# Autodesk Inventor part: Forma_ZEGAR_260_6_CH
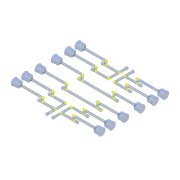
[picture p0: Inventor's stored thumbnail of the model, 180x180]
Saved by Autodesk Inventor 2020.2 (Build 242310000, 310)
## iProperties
Created: 2015-01
Part Number: Forma_ZEGAR_260_6_CH
Material: Ogólny
Document SubType Name: Modeling
Designer: F.Stasiak
Density: 1 g/cm^3
Appearance: Przezroczysty - niebieski
Catalog Web Link: www.expertbooks.pl
Manager: www.cadconsulting.pl
Company: Fabian Stasiak CAD Consulting
Author: F.Stasiak
Subject: Zbiór ćwiczeń. Autodesk Inventor 2020. Kurs Professional
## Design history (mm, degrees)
node "Płaszczyzna konstrukcyjna1"
node "Segment chłodzenia1"
  sketch "Szkic1"
    geometry: L1 (0, 0)-(0, -5.177); L2 (0, -5.177)-(6.924, -4.745); L3 (6.924, -4.745)-(6.924, -4); L4 (6.924, -4)-(149.076, -4); L5 (149.076, -4)-(149.076, -4.745); L6 (149.076, -4.745)-(156, -5.177); L7 (156, -5.177)-(156, 0); L8 (0, 0)-(156, 0)
    constraints: 16 end point, 4 perpendicular, 1 parallel
    dimensions: "d0" = 4 distance between parallel lines of L4 L8; "d1" = 6.92404 distance between parallel lines of L3 L1; "d2" = 6.92404 distance between parallel lines of L5 L7; "d3" = 93.5763 deg angle of L2 L3; "d4" = 0.74472 distance of L2.end L3.end; "d5" = 93.5763 deg angle of L6 L5; "d6" = 0.74472 distance of L4.end L5.end
  node "Punkt konstrukcyjny1"
  node "Oś konstrukcyjna1"
node "Płaszczyzna konstrukcyjna3"
node "Segment chłodzenia3"
  sketch "Szkic3"
    geometry: L1 (0, 0)-(0, -5.177); L2 (0, -5.177)-(6.924, -4.745); L3 (6.924, -4.745)-(6.924, -4); L4 (6.924, -4)-(68, -4); L5 (68, -4)-(70.403, 0); L6 (70.403, 0)-(68, 0); L7 (0, 0)-(68, 0)
    constraints: 14 end point, 2 perpendicular, 1 collinear, 1 parallel
    dimensions: "d18" = 4 distance between parallel lines of L4 L7; "d19" = 2.40344 distance of L5.end L6.end; "d20" = 6.92404 distance between parallel lines of L3 L1; "d21" = 93.5763 deg angle of L2 L3; "d22" = 0.74472 distance of L2.end L3.end; "d23" = 59 deg angle of L5 L7
  node "Punkt konstrukcyjny3"
  node "Oś konstrukcyjna3"
node "Płaszczyzna konstrukcyjna4"
node "Segment chłodzenia4"
  sketch "Szkic4"
    geometry: L1 (0, 0)-(0, -5.177); L2 (0, -5.177)-(6.924, -4.745); L3 (6.924, -4.745)-(6.924, -4); L4 (6.924, -4)-(68, -4); L5 (68, -4)-(70.403, 0); L6 (70.403, 0)-(68, 0); L7 (0, 0)-(68, 0)
    constraints: 14 end point, 2 perpendicular, 1 collinear, 1 parallel
    dimensions: "d26" = 4 distance between parallel lines of L4 L7; "d27" = 2.40344 distance of L5.end L6.end; "d28" = 6.92404 distance between parallel lines of L3 L1; "d29" = 93.5763 deg angle of L2 L3; "d30" = 0.74472 distance of L2.end L3.end; "d31" = 59 deg angle of L5 L7
  node "Punkt konstrukcyjny4"
  node "Oś konstrukcyjna4"
node "Płaszczyzna konstrukcyjna5"
node "Segment chłodzenia5"
  sketch "Szkic5"
    geometry: L1 (0, 0)-(0, -5.177); L2 (0, -5.177)-(6.924, -4.745); L3 (6.924, -4.745)-(6.924, -4); L4 (6.924, -4)-(75, -4); L5 (75, -4)-(77.403, 0); L6 (77.403, 0)-(75, 0); L7 (0, 0)-(75, 0)
    constraints: 14 end point, 2 perpendicular, 1 collinear, 1 parallel
    dimensions: "d34" = 4 distance between parallel lines of L4 L7; "d35" = 2.40344 distance of L5.end L6.end; "d36" = 6.92404 distance between parallel lines of L3 L1; "d37" = 93.5763 deg angle of L2 L3; "d38" = 0.74472 distance of L2.end L3.end; "d39" = 59 deg angle of L5 L7
  node "Punkt konstrukcyjny5"
  node "Oś konstrukcyjna5"
node "Płaszczyzna konstrukcyjna6"
node "Segment chłodzenia6"
  sketch "Szkic6"
    geometry: L1 (0, 0)-(0, -4); L2 (0, -4)-(7, -4); L3 (7, -4)-(9.403, 0); L4 (9.403, 0)-(7, 0); L5 (0, 0)-(7, 0)
    constraints: 10 end point, 1 collinear, 1 parallel, 1 perpendicular
    dimensions: "d42" = 4 distance between parallel lines of L2 L5; "d43" = 2.40344 distance of L3.end L4.end; "d44" = 59 deg angle of L3 L5
  node "Punkt konstrukcyjny6"
  node "Oś konstrukcyjna6"
node "Płaszczyzna konstrukcyjna7"
node "Segment chłodzenia7"
  sketch "Szkic7"
    geometry: L1 (0, 0)-(0, -4); L2 (0, -4)-(7, -4); L3 (7, -4)-(9.403, 0); L4 (9.403, 0)-(7, 0); L5 (0, 0)-(7, 0)
    constraints: 10 end point, 1 collinear, 1 parallel, 1 perpendicular
    dimensions: "d47" = 4 distance between parallel lines of L2 L5; "d48" = 2.40344 distance of L3.end L4.end; "d49" = 59 deg angle of L3 L5
  node "Punkt konstrukcyjny7"
  node "Oś konstrukcyjna7"
node "Płaszczyzna konstrukcyjna9"
node "Segment chłodzenia9"
  sketch "Szkic9"
    geometry: L1 (0, 0)-(0, -4); L2 (0, -4)-(12, -4); L3 (12, -4)-(14.403, 0); L4 (14.403, 0)-(12, 0); L5 (0, 0)-(12, 0)
    constraints: 10 end point, 1 collinear, 1 parallel, 1 perpendicular
    dimensions: "d57" = 4 distance between parallel lines of L2 L5; "d58" = 2.40344 distance of L3.end L4.end; "d59" = 59 deg angle of L3 L5
  node "Punkt konstrukcyjny9"
  node "Oś konstrukcyjna9"
node "Płaszczyzna konstrukcyjna10"
node "Segment chłodzenia10"
  sketch "Szkic10"
    geometry: L1 (0, 0)-(0, -4); L2 (0, -4)-(12, -4); L3 (12, -4)-(14.403, 0); L4 (14.403, 0)-(12, 0); L5 (0, 0)-(12, 0)
    constraints: 10 end point, 1 collinear, 1 parallel, 1 perpendicular
    dimensions: "d62" = 4 distance between parallel lines of L2 L5; "d63" = 2.40344 distance of L3.end L4.end; "d64" = 59 deg angle of L3 L5
  node "Punkt konstrukcyjny10"
  node "Oś konstrukcyjna10"
node "Płaszczyzna konstrukcyjna12"
node "Segment chłodzenia12"
  sketch "Szkic12"
    geometry: L1 (0, 0)-(0, -5.177); L2 (0, -5.177)-(6.924, -4.745); L3 (6.924, -4.745)-(6.924, -4); L4 (6.924, -4)-(68, -4); L5 (68, -4)-(70.403, 0); L6 (70.403, 0)-(68, 0); L7 (0, 0)-(68, 0)
    constraints: 14 end point, 2 perpendicular, 1 collinear, 1 parallel
    dimensions: "d72" = 4 distance between parallel lines of L4 L7; "d73" = 2.40344 distance of L5.end L6.end; "d74" = 6.92404 distance between parallel lines of L3 L1; "d75" = 93.5763 deg angle of L2 L3; "d76" = 0.74472 distance of L2.end L3.end; "d77" = 59 deg angle of L5 L7
  node "Punkt konstrukcyjny12"
  node "Oś konstrukcyjna12"
node "Płaszczyzna konstrukcyjna13"
node "Segment chłodzenia13"
  sketch "Szkic13"
    geometry: L1 (0, 0)-(0, -5.178); L2 (0, -5.178)-(6.924, -4.744); L3 (6.924, -4.744)-(6.924, -4); L4 (6.924, -4)-(68, -4); L5 (68, -4)-(70.403, 0); L6 (70.403, 0)-(68, 0); L7 (0, 0)-(68, 0)
    constraints: 14 end point, 2 perpendicular, 1 collinear, 1 parallel
    dimensions: "d80" = 4 distance between parallel lines of L4 L7; "d81" = 2.40344 distance of L5.end L6.end; "d82" = 6.924 distance between parallel lines of L3 L1; "d83" = 93.58 deg angle of L2 L3; "d84" = 0.7445 distance of L2.end L3.end; "d85" = 59 deg angle of L5 L7
  node "Punkt konstrukcyjny13"
  node "Oś konstrukcyjna13"
node "Płaszczyzna konstrukcyjna14"
node "Segment chłodzenia14"
  sketch "Szkic14"
    geometry: L1 (0, 0)-(0, -5.178); L2 (0, -5.178)-(6.924, -4.745); L3 (6.924, -4.745)-(6.924, -4); L4 (6.924, -4)-(75, -4); L5 (75, -4)-(77.403, 0); L6 (77.403, 0)-(75, 0); L7 (0, 0)-(75, 0)
    constraints: 14 end point, 2 perpendicular, 1 collinear, 1 parallel
    dimensions: "d88" = 4 distance between parallel lines of L4 L7; "d89" = 2.40344 distance of L5.end L6.end; "d90" = 6.924 distance between parallel lines of L3 L1; "d91" = 93.58 deg angle of L2 L3; "d92" = 0.7445 distance of L2.end L3.end; "d93" = 59 deg angle of L5 L7
  node "Punkt konstrukcyjny14"
  node "Oś konstrukcyjna14"
node "Płaszczyzna konstrukcyjna15"
node "Segment chłodzenia15"
  sketch "Szkic15"
    geometry: L1 (0, 0)-(0, -4); L2 (0, -4)-(7, -4); L3 (7, -4)-(9.403, 0); L4 (9.403, 0)-(7, 0); L5 (0, 0)-(7, 0)
    constraints: 10 end point, 1 collinear, 1 parallel, 1 perpendicular
    dimensions: "d96" = 4 distance between parallel lines of L2 L5; "d97" = 2.40344 distance of L3.end L4.end; "d98" = 59 deg angle of L3 L5
  node "Punkt konstrukcyjny15"
  node "Oś konstrukcyjna15"
node "Płaszczyzna konstrukcyjna16"
node "Segment chłodzenia16"
  sketch "Szkic16"
    geometry: L1 (0, 0)-(0, -4); L2 (0, -4)-(7, -4); L3 (7, -4)-(9.403, 0); L4 (9.403, 0)-(7, 0); L5 (0, 0)-(7, 0)
    constraints: 10 end point, 1 collinear, 1 parallel, 1 perpendicular
    dimensions: "d101" = 4 distance between parallel lines of L2 L5; "d102" = 2.40344 distance of L3.end L4.end; "d103" = 59 deg angle of L3 L5
  node "Punkt konstrukcyjny16"
  node "Oś konstrukcyjna16"
node "Płaszczyzna konstrukcyjna17"
node "Segment chłodzenia17"
  sketch "Szkic17"
    geometry: L1 (0, 0)-(0, -5.178); L2 (0, -5.178)-(6.924, -4.745); L3 (6.924, -4.745)-(6.924, -4); L4 (6.924, -4)-(149.076, -4); L5 (149.076, -4)-(149.076, -4.745); L6 (149.076, -4.745)-(156, -5.178); L7 (156, -5.178)-(156, 0); L8 (0, 0)-(156, 0)
    constraints: 16 end point, 4 perpendicular, 1 parallel
    dimensions: "d106" = 4 distance between parallel lines of L4 L8; "d107" = 6.924 distance between parallel lines of L3 L1; "d108" = 6.924 distance between parallel lines of L5 L7; "d109" = 93.58 deg angle of L2 L3; "d110" = 0.7445 distance of L2.end L3.end; "d111" = 93.58 deg angle of L6 L5; "d112" = 0.7445 distance of L4.end L5.end
  node "Punkt konstrukcyjny17"
  node "Oś konstrukcyjna17"
node "Płaszczyzna konstrukcyjna19"
node "Segment chłodzenia19"
  sketch "Szkic19"
    geometry: L1 (0, 0)-(0, -5.178); L2 (0, -5.178)-(6.924, -4.745); L3 (6.924, -4.745)-(6.924, -4); L4 (6.924, -4)-(68, -4); L5 (68, -4)-(68, 0); L6 (0, 0)-(68, 0)
    constraints: 12 end point, 3 perpendicular, 1 parallel
    dimensions: "d124" = 4 distance between parallel lines of L4 L6; "d125" = 6.924 distance between parallel lines of L3 L1; "d126" = 93.58 deg angle of L2 L3; "d127" = 0.7445 distance of L2.end L3.end
  node "Punkt konstrukcyjny19"
  node "Oś konstrukcyjna19"
node "Płaszczyzna konstrukcyjna20"
node "Segment chłodzenia20"
  sketch "Szkic20"
    geometry: L1 (0, 0)-(0, -5.178); L2 (0, -5.178)-(6.924, -4.745); L3 (6.924, -4.745)-(6.924, -4); L4 (6.924, -4)-(68, -4); L5 (68, -4)-(68, 0); L6 (0, 0)-(68, 0)
    constraints: 12 end point, 3 perpendicular, 1 parallel
    dimensions: "d130" = 4 distance between parallel lines of L4 L6; "d131" = 6.924 distance between parallel lines of L3 L1; "d132" = 93.58 deg angle of L2 L3; "d133" = 0.7445 distance of L2.end L3.end
  node "Punkt konstrukcyjny20"
  node "Oś konstrukcyjna20"
node "Płaszczyzna konstrukcyjna21"
node "Segment chłodzenia21"
  sketch "Szkic21"
    geometry: L1 (0, 0)-(0, -5.178); L2 (0, -5.178)-(6.924, -4.745); L3 (6.924, -4.745)-(6.924, -4); L4 (6.924, -4)-(75, -4); L5 (75, -4)-(75, 0); L6 (0, 0)-(75, 0)
    constraints: 12 end point, 3 perpendicular, 1 parallel
    dimensions: "d136" = 4 distance between parallel lines of L4 L6; "d137" = 6.924 distance between parallel lines of L3 L1; "d138" = 93.58 deg angle of L2 L3; "d139" = 0.7445 distance of L2.end L3.end
  node "Punkt konstrukcyjny21"
  node "Oś konstrukcyjna21"
node "Płaszczyzna konstrukcyjna22"
node "Segment chłodzenia22"
  sketch "Szkic22"
    geometry: L1 (0, 0)-(0, -5.178); L2 (0, -5.178)-(6.924, -4.744); L3 (6.924, -4.744)-(6.924, -4); L4 (6.924, -4)-(68, -4); L5 (68, -4)-(68, 0); L6 (0, 0)-(68, 0)
    constraints: 12 end point, 3 perpendicular, 1 parallel
    dimensions: "d142" = 4 distance between parallel lines of L4 L6; "d143" = 6.924 distance between parallel lines of L3 L1; "d144" = 93.58 deg angle of L2 L3; "d145" = 0.7445 distance of L2.end L3.end
  node "Punkt konstrukcyjny22"
  node "Oś konstrukcyjna22"
node "Płaszczyzna konstrukcyjna23"
node "Segment chłodzenia23"
  sketch "Szkic23"
    geometry: L1 (0, 0)-(0, -5.178); L2 (0, -5.178)-(6.924, -4.744); L3 (6.924, -4.744)-(6.924, -4); L4 (6.924, -4)-(68, -4); L5 (68, -4)-(68, 0); L6 (0, 0)-(68, 0)
    constraints: 12 end point, 3 perpendicular, 1 parallel
    dimensions: "d148" = 4 distance between parallel lines of L4 L6; "d149" = 6.924 distance between parallel lines of L3 L1; "d150" = 93.58 deg angle of L2 L3; "d151" = 0.7445 distance of L2.end L3.end
  node "Punkt konstrukcyjny23"
  node "Oś konstrukcyjna23"
node "Płaszczyzna konstrukcyjna24"
node "Segment chłodzenia24"
  sketch "Szkic24"
    geometry: L1 (0, 0)-(0, -5.178); L2 (0, -5.178)-(6.924, -4.745); L3 (6.924, -4.745)-(6.924, -4); L4 (6.924, -4)-(75, -4); L5 (75, -4)-(75, 0); L6 (0, 0)-(75, 0)
    constraints: 12 end point, 3 perpendicular, 1 parallel
    dimensions: "d154" = 4 distance between parallel lines of L4 L6; "d155" = 6.924 distance between parallel lines of L3 L1; "d156" = 93.58 deg angle of L2 L3; "d157" = 0.7445 distance of L2.end L3.end
  node "Punkt konstrukcyjny24"
  node "Oś konstrukcyjna24"
node "Płaszczyzna konstrukcyjna25"
node "Segment chłodzenia25"
  sketch "Szkic25"
    geometry: L1 (0, 0)-(0, -4); L2 (0, -4)-(12, -4); L3 (12, -4)-(12, 0); L4 (0, 0)-(12, 0)
    constraints: 8 end point, 2 perpendicular, 1 parallel
    dimensions: "d160" = 4 distance between parallel lines of L2 L4
  node "Punkt konstrukcyjny25"
  node "Oś konstrukcyjna25"
node "Płaszczyzna konstrukcyjna27"
node "Segment chłodzenia27"
  sketch "Szkic27"
    geometry: L1 (0, 0)-(0, -4); L2 (0, -4)-(12, -4); L3 (12, -4)-(12, 0); L4 (0, 0)-(12, 0)
    constraints: 8 end point, 2 perpendicular, 1 parallel
    dimensions: "d166" = 4 distance between parallel lines of L2 L4
  node "Punkt konstrukcyjny27"
  node "Oś konstrukcyjna27"
node "Płaszczyzna konstrukcyjna29"
node "Segment chłodzenia29"
  sketch "Szkic29"
    geometry: L1 (0, 0)-(0, -4); L2 (0, -4)-(7, -4); L3 (7, -4)-(7, 0); L4 (0, 0)-(7, 0)
    constraints: 8 end point, 2 perpendicular, 1 parallel
    dimensions: "d172" = 4 distance between parallel lines of L2 L4
  node "Punkt konstrukcyjny29"
  node "Oś konstrukcyjna29"
node "Płaszczyzna konstrukcyjna30"
node "Segment chłodzenia30"
  sketch "Szkic30"
    geometry: L1 (0, 0)-(0, -4); L2 (0, -4)-(7, -4); L3 (7, -4)-(7, 0); L4 (0, 0)-(7, 0)
    constraints: 8 end point, 2 perpendicular, 1 parallel
    dimensions: "d175" = 4 distance between parallel lines of L2 L4
  node "Punkt konstrukcyjny30"
  node "Oś konstrukcyjna30"
node "Płaszczyzna konstrukcyjna31"
node "Segment chłodzenia31"
  sketch "Szkic31"
    geometry: L1 (0, 0)-(0, -4); L2 (0, -4)-(7, -4); L3 (7, -4)-(7, 0); L4 (0, 0)-(7, 0)
    constraints: 8 end point, 2 perpendicular, 1 parallel
    dimensions: "d178" = 4 distance between parallel lines of L2 L4
  node "Punkt konstrukcyjny31"
  node "Oś konstrukcyjna31"
node "Płaszczyzna konstrukcyjna32"
node "Segment chłodzenia32"
  sketch "Szkic32"
    geometry: L1 (0, 0)-(0, -4); L2 (0, -4)-(7, -4); L3 (7, -4)-(7, 0); L4 (0, 0)-(7, 0)
    constraints: 8 end point, 2 perpendicular, 1 parallel
    dimensions: "d181" = 4 distance between parallel lines of L2 L4
  node "Punkt konstrukcyjny32"
  node "Oś konstrukcyjna32"
node "Płaszczyzna konstrukcyjna33"
node "Segment chłodzenia33"
  sketch "Szkic33"
    geometry: L1 (0, 0)-(0, -14.5); L2 (0, -14.5)-(2, -12.5); L3 (2, -12.5)-(20, -12.5); L4 (20, -12.5)-(20, -5.177); L5 (20, -5.177)-(26.924, -4.745); L6 (26.924, -4.745)-(26.924, -4); L7 (26.924, -4)-(115, -4); L8 (115, -4)-(117.403, 0); L9 (117.403, 0)-(115, 0); L10 (0, 0)-(115, 0)
    constraints: 20 end point, 3 perpendicular, 2 parallel, 1 collinear
    dimensions: "d184" = 4 distance between parallel lines of L7 L10; "d185" = 14.5 distance of L1.start L1.end; "d186" = 2.40344 distance of L8.end L9.end; "d187" = 12.5 distance between parallel lines of L3 L10; "d188" = 20 distance between parallel lines of L4 L1; "d189" = 26.92404 distance between parallel lines of L6 L1; "d190" = 93.5763 deg angle of L5 L6; "d191" = 0.74472 distance of L5.end L6.end; "d192" = 59 deg angle of L8 L10; "d193" = 45 deg angle of L2 L1
  node "Punkt konstrukcyjny33"
  node "Oś konstrukcyjna33"
node "Płaszczyzna konstrukcyjna34"
node "Segment chłodzenia34"
  sketch "Szkic34"
    geometry: L1 (0, 0)-(0, -4); L2 (0, -4)-(8, -4); L3 (8, -4)-(10.403, 0); L4 (10.403, 0)-(8, 0); L5 (0, 0)-(8, 0)
    constraints: 10 end point, 1 collinear, 1 parallel, 1 perpendicular
    dimensions: "d196" = 4 distance between parallel lines of L2 L5; "d197" = 2.40344 distance of L3.end L4.end; "d198" = 59 deg angle of L3 L5
  node "Punkt konstrukcyjny34"
  node "Oś konstrukcyjna34"
node "Płaszczyzna konstrukcyjna35"
node "Segment chłodzenia35"
  sketch "Szkic35"
    geometry: L1 (0, 0)-(0, -14.5); L2 (0, -14.5)-(2, -12.5); L3 (2, -12.5)-(20, -12.5); L4 (20, -12.5)-(20, -5.178); L5 (20, -5.178)-(26.924, -4.744); L6 (26.924, -4.744)-(26.924, -4); L7 (26.924, -4)-(115, -4); L8 (115, -4)-(117.403, 0); L9 (117.403, 0)-(115, 0); L10 (0, 0)-(115, 0)
    constraints: 20 end point, 3 perpendicular, 2 parallel, 1 collinear
    dimensions: "d201" = 4 distance between parallel lines of L7 L10; "d202" = 14.5 distance of L1.start L1.end; "d203" = 2.40344 distance of L8.end L9.end; "d204" = 12.5 distance between parallel lines of L3 L10; "d205" = 20 distance between parallel lines of L4 L1; "d206" = 26.924 distance between parallel lines of L6 L1; "d207" = 93.58 deg angle of L5 L6; "d208" = 0.7445 distance of L5.end L6.end; "d209" = 59 deg angle of L8 L10; "d210" = 45 deg angle of L2 L1
  node "Punkt konstrukcyjny35"
  node "Oś konstrukcyjna35"
node "Płaszczyzna konstrukcyjna36"
node "Segment chłodzenia36"
  sketch "Szkic36"
    geometry: L1 (0, 0)-(0, -14.5); L2 (0, -14.5)-(2, -12.5); L3 (2, -12.5)-(20, -12.5); L4 (20, -12.5)-(20, -5.178); L5 (20, -5.178)-(26.924, -4.745); L6 (26.924, -4.745)-(26.924, -4); L7 (26.924, -4)-(115, -4); L8 (115, -4)-(117.403, 0); L9 (117.403, 0)-(115, 0); L10 (0, 0)-(115, 0)
    constraints: 20 end point, 3 perpendicular, 2 parallel, 1 collinear
    dimensions: "d213" = 4 distance between parallel lines of L7 L10; "d214" = 14.5 distance of L1.start L1.end; "d215" = 2.40344 distance of L8.end L9.end; "d216" = 12.5 distance between parallel lines of L3 L10; "d217" = 20 distance between parallel lines of L4 L1; "d218" = 26.924 distance between parallel lines of L6 L1; "d219" = 93.58 deg angle of L5 L6; "d220" = 0.7445 distance of L5.end L6.end; "d221" = 59 deg angle of L8 L10; "d222" = 45 deg angle of L2 L1
  node "Punkt konstrukcyjny36"
  node "Oś konstrukcyjna36"
node "Płaszczyzna konstrukcyjna37"
node "Segment chłodzenia37"
  sketch "Szkic37"
    geometry: L1 (0, 0)-(0, -14.5); L2 (0, -14.5)-(2, -12.5); L3 (2, -12.5)-(20, -12.5); L4 (20, -12.5)-(20, -5.178); L5 (20, -5.178)-(26.924, -4.745); L6 (26.924, -4.745)-(26.924, -4); L7 (26.924, -4)-(115, -4); L8 (115, -4)-(117.403, 0); L9 (117.403, 0)-(115, 0); L10 (0, 0)-(115, 0)
    constraints: 20 end point, 3 perpendicular, 2 parallel, 1 collinear
    dimensions: "d225" = 4 distance between parallel lines of L7 L10; "d226" = 14.5 distance of L1.start L1.end; "d227" = 2.40344 distance of L8.end L9.end; "d228" = 12.5 distance between parallel lines of L3 L10; "d229" = 20 distance between parallel lines of L4 L1; "d230" = 26.924 distance between parallel lines of L6 L1; "d231" = 93.58 deg angle of L5 L6; "d232" = 0.7445 distance of L5.end L6.end; "d233" = 59 deg angle of L8 L10; "d234" = 45 deg angle of L2 L1
  node "Punkt konstrukcyjny37"
  node "Oś konstrukcyjna37"
node "Płaszczyzna konstrukcyjna38"
node "Segment chłodzenia38"
  sketch "Szkic38"
    geometry: L1 (0, 0)-(0, -14.5); L2 (0, -14.5)-(2, -12.5); L3 (2, -12.5)-(20, -12.5); L4 (20, -12.5)-(20, -5.178); L5 (20, -5.178)-(26.924, -4.745); L6 (26.924, -4.745)-(26.924, -4); L7 (26.924, -4)-(115, -4); L8 (115, -4)-(117.403, 0); L9 (117.403, 0)-(115, 0); L10 (0, 0)-(115, 0)
    constraints: 20 end point, 3 perpendicular, 2 parallel, 1 collinear
    dimensions: "d237" = 4 distance between parallel lines of L7 L10; "d238" = 14.5 distance of L1.start L1.end; "d239" = 2.40344 distance of L8.end L9.end; "d240" = 12.5 distance between parallel lines of L3 L10; "d241" = 20 distance between parallel lines of L4 L1; "d242" = 26.924 distance between parallel lines of L6 L1; "d243" = 93.58 deg angle of L5 L6; "d244" = 0.7445 distance of L5.end L6.end; "d245" = 59 deg angle of L8 L10; "d246" = 45 deg angle of L2 L1
  node "Punkt konstrukcyjny38"
  node "Oś konstrukcyjna38"
node "Płaszczyzna konstrukcyjna39"
node "Segment chłodzenia39"
  sketch "Szkic39"
    geometry: L1 (0, 0)-(0, -14.5); L2 (0, -14.5)-(2, -12.5); L3 (2, -12.5)-(20, -12.5); L4 (20, -12.5)-(20, -5.178); L5 (20, -5.178)-(26.924, -4.745); L6 (26.924, -4.745)-(26.924, -4); L7 (26.924, -4)-(115, -4); L8 (115, -4)-(117.403, 0); L9 (117.403, 0)-(115, 0); L10 (0, 0)-(115, 0)
    constraints: 20 end point, 3 perpendicular, 2 parallel, 1 collinear
    dimensions: "d249" = 4 distance between parallel lines of L7 L10; "d250" = 14.5 distance of L1.start L1.end; "d251" = 2.40344 distance of L8.end L9.end; "d252" = 12.5 distance between parallel lines of L3 L10; "d253" = 20 distance between parallel lines of L4 L1; "d254" = 26.924 distance between parallel lines of L6 L1; "d255" = 93.58 deg angle of L5 L6; "d256" = 0.7445 distance of L5.end L6.end; "d257" = 59 deg angle of L8 L10; "d258" = 45 deg angle of L2 L1
  node "Punkt konstrukcyjny39"
  node "Oś konstrukcyjna39"
node "Płaszczyzna konstrukcyjna40"
node "Segment chłodzenia40"
  sketch "Szkic40"
    geometry: L1 (0, 0)-(0, -14.5); L2 (0, -14.5)-(2, -12.5); L3 (2, -12.5)-(20, -12.5); L4 (20, -12.5)-(20, -5.178); L5 (20, -5.178)-(26.924, -4.745); L6 (26.924, -4.745)-(26.924, -4); L7 (26.924, -4)-(115, -4); L8 (115, -4)-(117.403, 0); L9 (117.403, 0)-(115, 0); L10 (0, 0)-(115, 0)
    constraints: 20 end point, 3 perpendicular, 2 parallel, 1 collinear
    dimensions: "d261" = 4 distance between parallel lines of L7 L10; "d262" = 14.5 distance of L1.start L1.end; "d263" = 2.40344 distance of L8.end L9.end; "d264" = 12.5 distance between parallel lines of L3 L10; "d265" = 20 distance between parallel lines of L4 L1; "d266" = 26.924 distance between parallel lines of L6 L1; "d267" = 93.58 deg angle of L5 L6; "d268" = 0.7445 distance of L5.end L6.end; "d269" = 59 deg angle of L8 L10; "d270" = 45 deg angle of L2 L1
  node "Punkt konstrukcyjny40"
  node "Oś konstrukcyjna40"
node "Płaszczyzna konstrukcyjna41"
node "Segment chłodzenia41"
  sketch "Szkic41"
    geometry: L1 (0, 0)-(0, -14.5); L2 (0, -14.5)-(2, -12.5); L3 (2, -12.5)-(20, -12.5); L4 (20, -12.5)-(20, -5.178); L5 (20, -5.178)-(26.924, -4.745); L6 (26.924, -4.745)-(26.924, -4); L7 (26.924, -4)-(115, -4); L8 (115, -4)-(117.403, 0); L9 (117.403, 0)-(115, 0); L10 (0, 0)-(115, 0)
    constraints: 20 end point, 3 perpendicular, 2 parallel, 1 collinear
    dimensions: "d273" = 4 distance between parallel lines of L7 L10; "d274" = 14.5 distance of L1.start L1.end; "d275" = 2.40344 distance of L8.end L9.end; "d276" = 12.5 distance between parallel lines of L3 L10; "d277" = 20 distance between parallel lines of L4 L1; "d278" = 26.924 distance between parallel lines of L6 L1; "d279" = 93.58 deg angle of L5 L6; "d280" = 0.7445 distance of L5.end L6.end; "d281" = 59 deg angle of L8 L10; "d282" = 45 deg angle of L2 L1
  node "Punkt konstrukcyjny41"
  node "Oś konstrukcyjna41"
node "Płaszczyzna konstrukcyjna42"
node "Segment chłodzenia42"
  sketch "Szkic42"
    geometry: L1 (0, 0)-(0, -14.5); L2 (0, -14.5)-(2, -12.5); L3 (2, -12.5)-(20, -12.5); L4 (20, -12.5)-(20, -5.178); L5 (20, -5.178)-(26.924, -4.745); L6 (26.924, -4.745)-(26.924, -4); L7 (26.924, -4)-(115, -4); L8 (115, -4)-(117.403, 0); L9 (117.403, 0)-(115, 0); L10 (0, 0)-(115, 0)
    constraints: 20 end point, 3 perpendicular, 2 parallel, 1 collinear
    dimensions: "d285" = 4 distance between parallel lines of L7 L10; "d286" = 14.5 distance of L1.start L1.end; "d287" = 2.40344 distance of L8.end L9.end; "d288" = 12.5 distance between parallel lines of L3 L10; "d289" = 20 distance between parallel lines of L4 L1; "d290" = 26.924 distance between parallel lines of L6 L1; "d291" = 93.58 deg angle of L5 L6; "d292" = 0.7445 distance of L5.end L6.end; "d293" = 59 deg angle of L8 L10; "d294" = 45 deg angle of L2 L1
  node "Punkt konstrukcyjny42"
  node "Oś konstrukcyjna42"
node "Płaszczyzna konstrukcyjna43"
node "Segment chłodzenia43"
  sketch "Szkic43"
    geometry: L1 (0, 0)-(0, -14.5); L2 (0, -14.5)-(2, -12.5); L3 (2, -12.5)-(20, -12.5); L4 (20, -12.5)-(20, -5.178); L5 (20, -5.178)-(26.924, -4.745); L6 (26.924, -4.745)-(26.924, -4); L7 (26.924, -4)-(115, -4); L8 (115, -4)-(117.403, 0); L9 (117.403, 0)-(115, 0); L10 (0, 0)-(115, 0)
    constraints: 20 end point, 3 perpendicular, 2 parallel, 1 collinear
    dimensions: "d297" = 4 distance between parallel lines of L7 L10; "d298" = 14.5 distance of L1.start L1.end; "d299" = 2.40344 distance of L8.end L9.end; "d300" = 12.5 distance between parallel lines of L3 L10; "d301" = 20 distance between parallel lines of L4 L1; "d302" = 26.924 distance between parallel lines of L6 L1; "d303" = 93.58 deg angle of L5 L6; "d304" = 0.7445 distance of L5.end L6.end; "d305" = 59 deg angle of L8 L10; "d306" = 45 deg angle of L2 L1
  node "Punkt konstrukcyjny43"
  node "Oś konstrukcyjna43"
node "Płaszczyzna konstrukcyjna44"
node "Segment chłodzenia44"
  sketch "Szkic44"
    geometry: L1 (0, 0)-(0, -14.5); L2 (0, -14.5)-(2, -12.5); L3 (2, -12.5)-(20, -12.5); L4 (20, -12.5)-(20, -5.178); L5 (20, -5.178)-(26.924, -4.745); L6 (26.924, -4.745)-(26.924, -4); L7 (26.924, -4)-(115, -4); L8 (115, -4)-(117.403, 0); L9 (117.403, 0)-(115, 0); L10 (0, 0)-(115, 0)
    constraints: 20 end point, 3 perpendicular, 2 parallel, 1 collinear
    dimensions: "d309" = 4 distance between parallel lines of L7 L10; "d310" = 14.5 distance of L1.start L1.end; "d311" = 2.40344 distance of L8.end L9.end; "d312" = 12.5 distance between parallel lines of L3 L10; "d313" = 20 distance between parallel lines of L4 L1; "d314" = 26.924 distance between parallel lines of L6 L1; "d315" = 93.58 deg angle of L5 L6; "d316" = 0.7445 distance of L5.end L6.end; "d317" = 59 deg angle of L8 L10; "d318" = 45 deg angle of L2 L1
  node "Punkt konstrukcyjny44"
  node "Oś konstrukcyjna44"
node "Płaszczyzna konstrukcyjna45"
node "Segment chłodzenia45"
  sketch "Szkic45"
    geometry: L1 (0, 0)-(0, -14.5); L2 (0, -14.5)-(2, -12.5); L3 (2, -12.5)-(20, -12.5); L4 (20, -12.5)-(20, -5.178); L5 (20, -5.178)-(26.924, -4.745); L6 (26.924, -4.745)-(26.924, -4); L7 (26.924, -4)-(115, -4); L8 (115, -4)-(117.403, 0); L9 (117.403, 0)-(115, 0); L10 (0, 0)-(115, 0)
    constraints: 20 end point, 3 perpendicular, 2 parallel, 1 collinear
    dimensions: "d321" = 4 distance between parallel lines of L7 L10; "d322" = 14.5 distance of L1.start L1.end; "d323" = 2.40344 distance of L8.end L9.end; "d324" = 12.5 distance between parallel lines of L3 L10; "d325" = 20 distance between parallel lines of L4 L1; "d326" = 26.924 distance between parallel lines of L6 L1; "d327" = 93.58 deg angle of L5 L6; "d328" = 0.7445 distance of L5.end L6.end; "d329" = 59 deg angle of L8 L10; "d330" = 45 deg angle of L2 L1
  node "Punkt konstrukcyjny45"
  node "Oś konstrukcyjna45"
node "Płaszczyzna konstrukcyjna46"
node "Segment chłodzenia46"
  sketch "Szkic46"
    geometry: L1 (0, 0)-(0, -4); L2 (0, -4)-(8, -4); L3 (8, -4)-(10.403, 0); L4 (10.403, 0)-(8, 0); L5 (0, 0)-(8, 0)
    constraints: 10 end point, 1 collinear, 1 parallel, 1 perpendicular
    dimensions: "d333" = 4 distance between parallel lines of L2 L5; "d334" = 2.40344 distance of L3.end L4.end; "d335" = 59 deg angle of L3 L5
  node "Punkt konstrukcyjny46"
  node "Oś konstrukcyjna46"
node "Płaszczyzna konstrukcyjna47"
node "Segment chłodzenia47"
  sketch "Szkic47"
    geometry: L1 (0, 0)-(0, -4); L2 (0, -4)-(8, -4); L3 (8, -4)-(10.403, 0); L4 (10.403, 0)-(8, 0); L5 (0, 0)-(8, 0)
    constraints: 10 end point, 1 collinear, 1 parallel, 1 perpendicular
    dimensions: "d338" = 4 distance between parallel lines of L2 L5; "d339" = 2.40344 distance of L3.end L4.end; "d340" = 59 deg angle of L3 L5
  node "Punkt konstrukcyjny47"
  node "Oś konstrukcyjna47"
node "Płaszczyzna konstrukcyjna48"
node "Segment chłodzenia48"
  sketch "Szkic48"
    geometry: L1 (0, 0)-(0, -4); L2 (0, -4)-(8, -4); L3 (8, -4)-(10.403, 0); L4 (10.403, 0)-(8, 0); L5 (0, 0)-(8, 0)
    constraints: 10 end point, 1 collinear, 1 parallel, 1 perpendicular
    dimensions: "d343" = 4 distance between parallel lines of L2 L5; "d344" = 2.40344 distance of L3.end L4.end; "d345" = 59 deg angle of L3 L5
  node "Punkt konstrukcyjny48"
  node "Oś konstrukcyjna48"
node "Płaszczyzna konstrukcyjna49"
node "Segment chłodzenia49"
  sketch "Szkic49"
    geometry: L1 (0, 0)-(0, -4); L2 (0, -4)-(8, -4); L3 (8, -4)-(10.403, 0); L4 (10.403, 0)-(8, 0); L5 (0, 0)-(8, 0)
    constraints: 10 end point, 1 collinear, 1 parallel, 1 perpendicular
    dimensions: "d348" = 4 distance between parallel lines of L2 L5; "d349" = 2.40344 distance of L3.end L4.end; "d350" = 59 deg angle of L3 L5
  node "Punkt konstrukcyjny49"
  node "Oś konstrukcyjna49"
node "Płaszczyzna konstrukcyjna50"
node "Segment chłodzenia50"
  sketch "Szkic50"
    geometry: L1 (0, 0)-(0, -4); L2 (0, -4)-(8, -4); L3 (8, -4)-(10.403, 0); L4 (10.403, 0)-(8, 0); L5 (0, 0)-(8, 0)
    constraints: 10 end point, 1 collinear, 1 parallel, 1 perpendicular
    dimensions: "d353" = 4 distance between parallel lines of L2 L5; "d354" = 2.40344 distance of L3.end L4.end; "d355" = 59 deg angle of L3 L5
  node "Punkt konstrukcyjny50"
  node "Oś konstrukcyjna50"
node "Płaszczyzna konstrukcyjna51"
node "Segment chłodzenia51"
  sketch "Szkic51"
    geometry: L1 (0, 0)-(0, -4); L2 (0, -4)-(8, -4); L3 (8, -4)-(10.403, 0); L4 (10.403, 0)-(8, 0); L5 (0, 0)-(8, 0)
    constraints: 10 end point, 1 collinear, 1 parallel, 1 perpendicular
    dimensions: "d358" = 4 distance between parallel lines of L2 L5; "d359" = 2.40344 distance of L3.end L4.end; "d360" = 59 deg angle of L3 L5
  node "Punkt konstrukcyjny51"
  node "Oś konstrukcyjna51"
node "Płaszczyzna konstrukcyjna52"
node "Segment chłodzenia52"
  sketch "Szkic52"
    geometry: L1 (0, 0)-(0, -4); L2 (0, -4)-(8, -4); L3 (8, -4)-(10.403, 0); L4 (10.403, 0)-(8, 0); L5 (0, 0)-(8, 0)
    constraints: 10 end point, 1 collinear, 1 parallel, 1 perpendicular
    dimensions: "d363" = 4 distance between parallel lines of L2 L5; "d364" = 2.40344 distance of L3.end L4.end; "d365" = 59 deg angle of L3 L5
  node "Punkt konstrukcyjny52"
  node "Oś konstrukcyjna52"
node "Płaszczyzna konstrukcyjna53"
node "Segment chłodzenia53"
  sketch "Szkic53"
    geometry: L1 (0, 0)-(0, -4); L2 (0, -4)-(8, -4); L3 (8, -4)-(10.403, 0); L4 (10.403, 0)-(8, 0); L5 (0, 0)-(8, 0)
    constraints: 10 end point, 1 collinear, 1 parallel, 1 perpendicular
    dimensions: "d368" = 4 distance between parallel lines of L2 L5; "d369" = 2.40344 distance of L3.end L4.end; "d370" = 59 deg angle of L3 L5
  node "Punkt konstrukcyjny53"
  node "Oś konstrukcyjna53"
node "Płaszczyzna konstrukcyjna54"
node "Segment chłodzenia54"
  sketch "Szkic54"
    geometry: L1 (0, 0)-(0, -4); L2 (0, -4)-(8, -4); L3 (8, -4)-(10.403, 0); L4 (10.403, 0)-(8, 0); L5 (0, 0)-(8, 0)
    constraints: 10 end point, 1 collinear, 1 parallel, 1 perpendicular
    dimensions: "d373" = 4 distance between parallel lines of L2 L5; "d374" = 2.40344 distance of L3.end L4.end; "d375" = 59 deg angle of L3 L5
  node "Punkt konstrukcyjny54"
  node "Oś konstrukcyjna54"
node "Płaszczyzna konstrukcyjna55"
node "Segment chłodzenia55"
  sketch "Szkic55"
    geometry: L1 (0, 0)-(0, -4); L2 (0, -4)-(8, -4); L3 (8, -4)-(10.403, 0); L4 (10.403, 0)-(8, 0); L5 (0, 0)-(8, 0)
    constraints: 10 end point, 1 collinear, 1 parallel, 1 perpendicular
    dimensions: "d378" = 4 distance between parallel lines of L2 L5; "d379" = 2.40344 distance of L3.end L4.end; "d380" = 59 deg angle of L3 L5
  node "Punkt konstrukcyjny55"
  node "Oś konstrukcyjna55"
node "Płaszczyzna konstrukcyjna56"
node "Segment chłodzenia56"
  sketch "Szkic56"
    geometry: L1 (0, 0)-(0, -4); L2 (0, -4)-(8, -4); L3 (8, -4)-(10.403, 0); L4 (10.403, 0)-(8, 0); L5 (0, 0)-(8, 0)
    constraints: 10 end point, 1 collinear, 1 parallel, 1 perpendicular
    dimensions: "d383" = 4 distance between parallel lines of L2 L5; "d384" = 2.40344 distance of L3.end L4.end; "d385" = 59 deg angle of L3 L5
  node "Punkt konstrukcyjny56"
  node "Oś konstrukcyjna56"
node "Bryła1"
revolve "Obrót1" stored, may be unused: angle "d7" = 0 deg
body "Srf1"
revolve "Obrót3" stored, may be unused: angle "d24" = 0 deg
body "Srf3"
revolve "Obrót4" stored, may be unused: angle "d32" = 0 deg
body "Srf4"
revolve "Obrót5" stored, may be unused: angle "d40" = 0 deg
body "Srf5"
revolve "Obrót6" stored, may be unused: angle "d45" = 0 deg
body "Srf6"
revolve "Obrót7" stored, may be unused: angle "d50" = 0 deg
body "Srf7"
revolve "Obrót9" stored, may be unused: angle "d60" = 0 deg
body "Srf9"
revolve "Obrót10" stored, may be unused: angle "d65" = 0 deg
body "Srf10"
revolve "Obrót12" stored, may be unused: angle "d78" = 0 deg
body "Srf12"
revolve "Obrót13" stored, may be unused: angle "d86" = 0 deg
body "Srf13"
revolve "Obrót14" stored, may be unused: angle "d94" = 0 deg
body "Srf14"
revolve "Obrót15" stored, may be unused: angle "d99" = 0 deg
body "Srf15"
revolve "Obrót16" stored, may be unused: angle "d104" = 0 deg
body "Srf16"
revolve "Obrót17" stored, may be unused: angle "d113" = 0 deg
body "Srf17"
revolve "Obrót19" stored, may be unused: angle "d128" = 0 deg
body "Srf19"
revolve "Obrót20" stored, may be unused: angle "d134" = 0 deg
body "Srf20"
revolve "Obrót21" stored, may be unused: angle "d140" = 0 deg
body "Srf21"
revolve "Obrót22" stored, may be unused: angle "d146" = 0 deg
body "Srf22"
revolve "Obrót23" stored, may be unused: angle "d152" = 0 deg
body "Srf23"
revolve "Obrót24" stored, may be unused: angle "d158" = 0 deg
body "Srf24"
revolve "Obrót25" stored, may be unused: angle "d161" = 0 deg
body "Srf25"
revolve "Obrót27" stored, may be unused: angle "d167" = 0 deg
body "Srf27"
revolve "Obrót29" stored, may be unused: angle "d173" = 0 deg
body "Srf29"
revolve "Obrót30" stored, may be unused: angle "d176" = 0 deg
body "Srf30"
revolve "Obrót31" stored, may be unused: angle "d179" = 0 deg
body "Srf31"
revolve "Obrót32" stored, may be unused: angle "d182" = 0 deg
body "Srf32"
revolve "Obrót33" stored, may be unused: angle "d194" = 0 deg
body "Srf33"
revolve "Obrót34" stored, may be unused: angle "d199" = 0 deg
body "Srf34"
revolve "Obrót35" stored, may be unused: angle "d211" = 0 deg
body "Srf35"
revolve "Obrót36" stored, may be unused: angle "d223" = 0 deg
body "Srf36"
revolve "Obrót37" stored, may be unused: angle "d235" = 0 deg
body "Srf37"
revolve "Obrót38" stored, may be unused: angle "d247" = 0 deg
body "Srf38"
revolve "Obrót39" stored, may be unused: angle "d259" = 0 deg
body "Srf39"
revolve "Obrót40" stored, may be unused: angle "d271" = 0 deg
body "Srf40"
revolve "Obrót41" stored, may be unused: angle "d283" = 0 deg
body "Srf41"
revolve "Obrót42" stored, may be unused: angle "d295" = 0 deg
body "Srf42"
revolve "Obrót43" stored, may be unused: angle "d307" = 0 deg
body "Srf43"
revolve "Obrót44" stored, may be unused: angle "d319" = 0 deg
body "Srf44"
revolve "Obrót45" stored, may be unused: angle "d331" = 0 deg
body "Srf45"
revolve "Obrót46" stored, may be unused: angle "d336" = 0 deg
body "Srf46"
revolve "Obrót47" stored, may be unused: angle "d341" = 0 deg
body "Srf47"
revolve "Obrót48" stored, may be unused: angle "d346" = 0 deg
body "Srf48"
revolve "Obrót49" stored, may be unused: angle "d351" = 0 deg
body "Srf49"
revolve "Obrót50" stored, may be unused: angle "d356" = 0 deg
body "Srf50"
revolve "Obrót51" stored, may be unused: angle "d361" = 0 deg
body "Srf51"
revolve "Obrót52" stored, may be unused: angle "d366" = 0 deg
body "Srf52"
revolve "Obrót53" stored, may be unused: angle "d371" = 0 deg
body "Srf53"
revolve "Obrót54" stored, may be unused: angle "d376" = 0 deg
body "Srf54"
revolve "Obrót55" stored, may be unused: angle "d381" = 0 deg
body "Srf55"
revolve "Obrót56" stored, may be unused: angle "d386" = 0 deg
body "Srf56"
feature "PowObrotowa1" dims angle "d8" = 0 deg
feature "PowObrotowa3" dims angle "d25" = 0 deg
feature "PowObrotowa4" dims angle "d33" = 0 deg
feature "PowObrotowa5" dims angle "d41" = 0 deg
feature "PowObrotowa6" dims angle "d46" = 0 deg
feature "PowObrotowa7" dims angle "d51" = 0 deg
feature "PowObrotowa9" dims angle "d61" = 0 deg
feature "PowObrotowa10" dims angle "d66" = 0 deg
feature "PowObrotowa12" dims angle "d79" = 0 deg
feature "PowObrotowa13" dims angle "d87" = 0 deg
feature "PowObrotowa14" dims angle "d95" = 0 deg
feature "PowObrotowa15" dims angle "d100" = 0 deg
feature "PowObrotowa16" dims angle "d105" = 0 deg
feature "PowObrotowa17" dims angle "d114" = 0 deg
feature "PowObrotowa19" dims angle "d129" = 0 deg
feature "PowObrotowa20" dims angle "d135" = 0 deg
feature "PowObrotowa21" dims angle "d141" = 0 deg
feature "PowObrotowa22" dims angle "d147" = 0 deg
feature "PowObrotowa23" dims angle "d153" = 0 deg
feature "PowObrotowa24" dims angle "d159" = 0 deg
feature "PowObrotowa25" dims angle "d162" = 0 deg
feature "PowObrotowa27" dims angle "d168" = 0 deg
feature "PowObrotowa29" dims angle "d174" = 0 deg
feature "PowObrotowa30" dims angle "d177" = 0 deg
feature "PowObrotowa31" dims angle "d180" = 0 deg
feature "PowObrotowa32" dims angle "d183" = 0 deg
feature "PowObrotowa33" dims angle "d195" = 0 deg
feature "PowObrotowa34" dims angle "d200" = 0 deg
feature "PowObrotowa35" dims angle "d212" = 0 deg
feature "PowObrotowa36" dims angle "d224" = 0 deg
feature "PowObrotowa37" dims angle "d236" = 0 deg
feature "PowObrotowa38" dims angle "d248" = 0 deg
feature "PowObrotowa39" dims angle "d260" = 0 deg
feature "PowObrotowa40" dims angle "d272" = 0 deg
feature "PowObrotowa41" dims angle "d284" = 0 deg
feature "PowObrotowa42" dims angle "d296" = 0 deg
feature "PowObrotowa43" dims angle "d308" = 0 deg
feature "PowObrotowa44" dims angle "d320" = 0 deg
feature "PowObrotowa45" dims angle "d332" = 0 deg
feature "PowObrotowa46" dims angle "d337" = 0 deg
feature "PowObrotowa47" dims angle "d342" = 0 deg
feature "PowObrotowa48" dims angle "d347" = 0 deg
feature "PowObrotowa49" dims angle "d352" = 0 deg
feature "PowObrotowa50" dims angle "d357" = 0 deg
feature "PowObrotowa51" dims angle "d362" = 0 deg
feature "PowObrotowa52" dims angle "d367" = 0 deg
feature "PowObrotowa53" dims angle "d372" = 0 deg
feature "PowObrotowa54" dims angle "d377" = 0 deg
feature "PowObrotowa55" dims angle "d382" = 0 deg
feature "PowObrotowa56" dims angle "d387" = 0 deg
